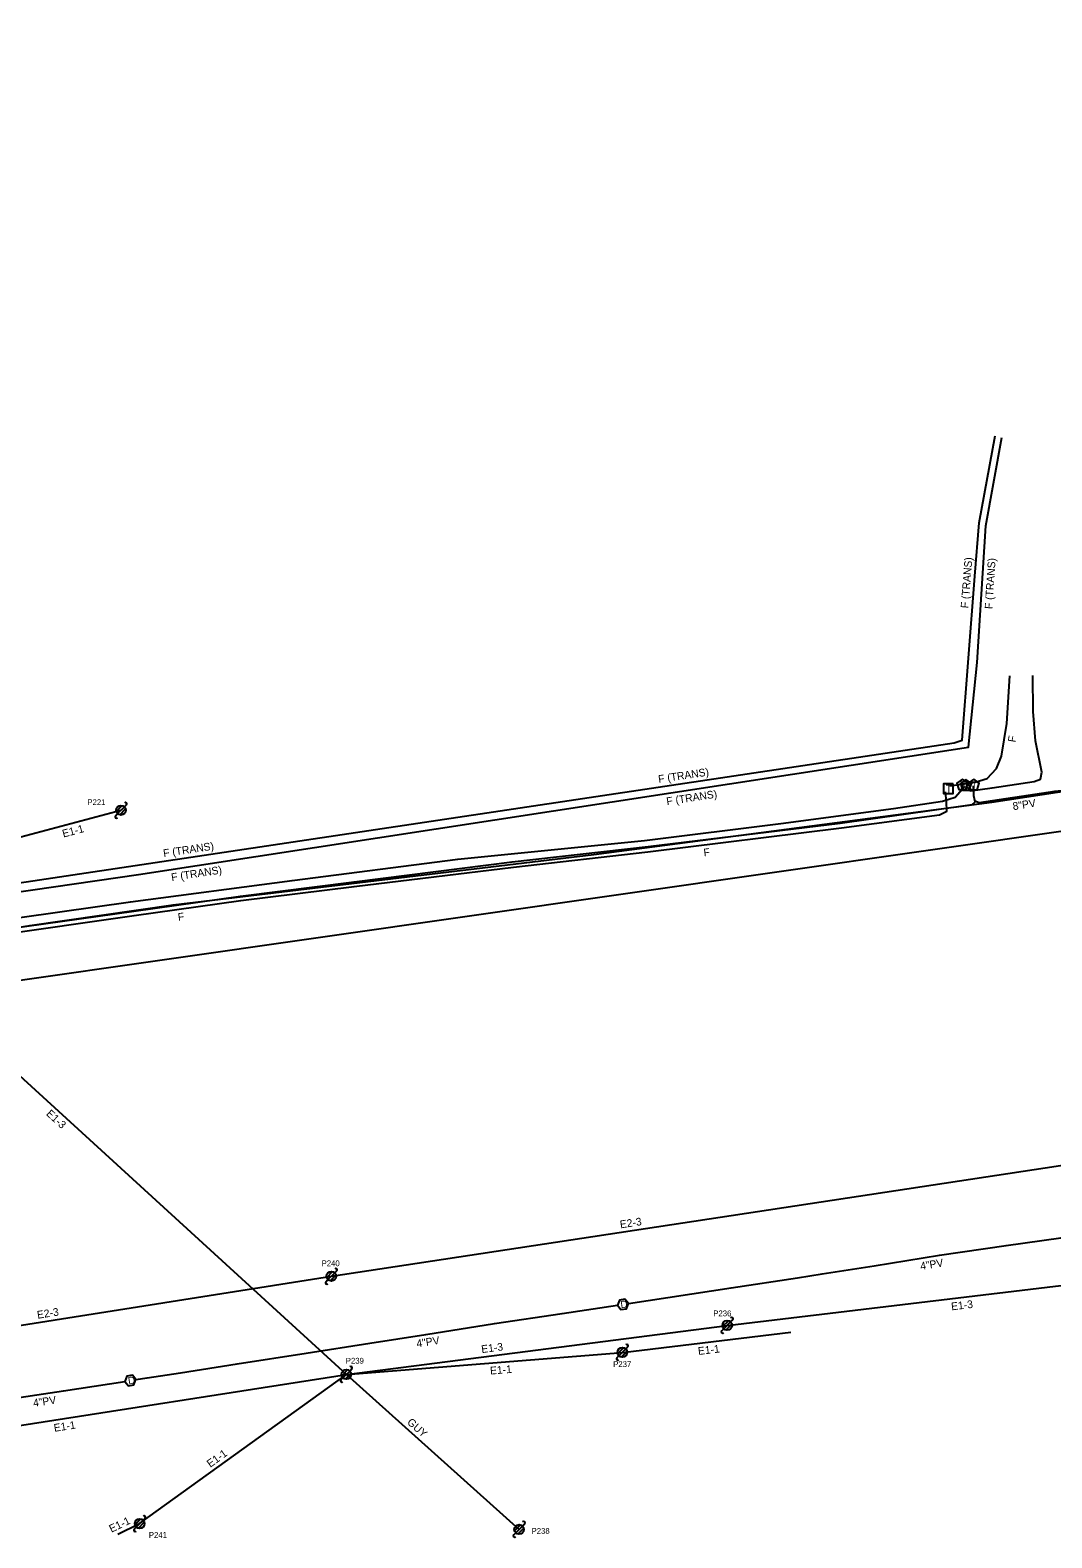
# Model space of a CAD drawing. Extents: x 1614474 to 1865144, y 1098877 to 1212550.
# Drawn here: x 1776287 to 1776816, y 1179819 to 1180599 of the extents above; entities that cross this region are included whole.
import ezdxf

# ---------------------------------------------------------------- set-up
doc = ezdxf.new("R2010")
doc.units = 0
for name, color, linetype in [('BFUSER_FIBERSPAN', 7, 'Continuous'), ('RD_EX_SU_H2O', 7, 'Continuous'), ('RD_EX_SU_Ovhd', 7, 'Continuous'), ('RD_EX_SU_Pole', 7, 'Continuous'), ('RD_EX_SU_Telecom', 7, 'Continuous'), ('RD_EX_SU_TX_H2O', 7, 'Continuous'), ('RD_EX_SU_TX_Pole', 7, 'Continuous'), ('RD_EX_SU_TX_Telecom', 7, 'Continuous')]:
    doc.layers.add(name, color=color, linetype=linetype)

# ---------------------------------------------------------------- blocks, each defined once
blk = doc.blocks.new('SUE_PP')
at = {"layer": 'RD_EX_SU_Pole'}
for p, q in [((-2.41, -0.65), (0.65, 2.41)), ((-1.77, -1.77), (1.77, 1.77)), ((-0.65, -2.41), (2.41, 0.65)), ((1.77, 1.77), (2.83, 2.83)), ((-2.83, -2.83), (-1.77, -1.77))]:
    blk.add_line(p, q, dxfattribs=at)
blk.add_circle((0, 0), 2.5, dxfattribs=at)
for centre, start, end in [((2.3, 3.36), 315, 135), ((-2.3, -3.36), 135, 315)]:
    blk.add_arc(centre, 0.75, start, end, dxfattribs=at)
blk = doc.blocks.new('SUE_TPP')
at = {"layer": 'RD_EX_SU_Telecom'}
blk.add_lwpolyline([(0, 3), (-2.85, 0.93), (-1.76, -2.43), (1.76, -2.43), (2.85, 0.93)], close=True, dxfattribs=at)
blk.add_text('T', height=3.75, dxfattribs=at).set_placement((-1.25, -1.88))
blk = doc.blocks.new('SUE_THH')
at = {"layer": 'RD_EX_SU_Telecom'}
blk.add_lwpolyline([(2.5, 2.5), (-2.5, 2.5), (-2.5, -2.5), (2.5, -2.5)], close=True, dxfattribs=at)
blk.add_text('T', height=4, dxfattribs=at).set_placement((-1.34, -2))

msp = doc.modelspace()

# ---------------------------------------------------------------- linework, layer by layer
at = {"layer": 'BFUSER_FIBERSPAN'}
msp.add_lwpolyline([(1776119.38, 1180084.52), (1776909.44, 1180197.58), (1777549.89, 1180288.26), (1777793.65, 1180334.21), (1778099.34, 1180399.49), (1778312.74, 1180438.72), (1779456.83, 1180598.99)], dxfattribs=at)
at = {"layer": 'RD_EX_SU_H2O'}
for points in [[(1775079.31, 1179947.86), (1775099.56, 1179951.26), (1775135.1, 1179956.75), (1775200.12, 1179966.22), (1775230.46, 1179971.15), (1775265.28, 1179976.78), (1775296.44, 1179981.42), (1775327.06, 1179986.33), (1775627.47, 1180033.75), (1775910.53, 1180076.48), (1776287.14, 1180136.1), (1776361.29, 1180146.68), (1776578.76, 1180172.75), (1776784.59, 1180199.86), (1777026.8, 1180236.7)], [(1776596.66, 1179940.56), (1776649.72, 1179948.66), (1776649.88, 1179948.69), (1776684.14, 1179953.92), (1776696.94, 1179955.9), (1776723.7, 1179960.03), (1776757.53, 1179965.55), (1776792.08, 1179970.65), (1776820.25, 1179974.64), (1776851.76, 1179980.08), (1776859.59, 1179981.3)], [(1776342.02, 1179901.23), (1776347.84, 1179902.14), (1776365.13, 1179904.83), (1776394.3, 1179909.43), (1776429.97, 1179914.93), (1776462.88, 1179920.06), (1776491.84, 1179924.63), (1776527.49, 1179930.19), (1776562.4, 1179935.51), (1776590.95, 1179939.71)], [(1776104.82, 1179864.77), (1776140.68, 1179869.96), (1776175.04, 1179875.44), (1776175.54, 1179875.52), (1776206.34, 1179880.25), (1776240.64, 1179885.5), (1776271.17, 1179890.42), (1776304.63, 1179895.52), (1776336.21, 1179900.32), (1776336.32, 1179900.34)]]:
    msp.add_lwpolyline(points, dxfattribs=at)
for points in [[(1776596.66, 1179940.56), (1776594.87, 1179942.82), (1776592.01, 1179942.4), (1776590.95, 1179939.71), (1776592.74, 1179937.45), (1776595.6, 1179937.87)], [(1776342.02, 1179901.23), (1776340.22, 1179903.48), (1776337.37, 1179903.05), (1776336.32, 1179900.36), (1776338.12, 1179898.11), (1776340.97, 1179898.54)]]:
    msp.add_lwpolyline(points, close=True, dxfattribs=at)
at = {"layer": 'RD_EX_SU_Ovhd'}
for p, q in [((1776282.53, 1180181.83), (1776334.27, 1180195.67)), ((1776171.93, 1180158.93), (1776450.84, 1179903.93)), ((1776443.07, 1179954.72), (1776825.82, 1180012.85)), ((1776195.31, 1179915.49), (1776443.07, 1179954.72)), ((1776647.76, 1179929.28), (1776854.89, 1179953.96)), ((1776450.84, 1179903.93), (1776647.76, 1179929.28)), ((1776593.56, 1179915.33), (1776680.72, 1179925.74)), ((1776450.84, 1179903.93), (1776593.56, 1179915.33)), ((1776170.06, 1179860.01), (1776450.84, 1179903.93)), ((1776343.93, 1179826.81), (1776450.84, 1179903.93)), ((1776450.84, 1179903.93), (1776540.18, 1179823.77)), ((1776332.61, 1179821.4), (1776343.93, 1179826.81))]:
    msp.add_line(p, q, dxfattribs=at)
at = {"layer": 'RD_EX_SU_Pole'}
for p, q in [((1776331.86, 1180195.02), (1776334.92, 1180198.09)), ((1776332.51, 1180193.9), (1776336.04, 1180197.44)), ((1776336.04, 1180197.44), (1776337.1, 1180198.5)), ((1776331.44, 1180192.84), (1776332.51, 1180193.9)), ((1776333.63, 1180193.26), (1776336.69, 1180196.32)), ((1776440.66, 1179954.07), (1776443.72, 1179957.13)), ((1776441.3, 1179952.95), (1776444.84, 1179956.48)), ((1776444.84, 1179956.48), (1776445.9, 1179957.54)), ((1776440.24, 1179951.89), (1776441.3, 1179952.95)), ((1776442.42, 1179952.3), (1776445.49, 1179955.36)), ((1776644.94, 1179926.45), (1776646, 1179927.51)), ((1776645.35, 1179928.63), (1776648.41, 1179931.7)), ((1776646, 1179927.51), (1776649.53, 1179931.05)), ((1776647.12, 1179926.87), (1776650.18, 1179929.93)), ((1776649.53, 1179931.05), (1776650.59, 1179932.11)), ((1776591.15, 1179914.68), (1776594.21, 1179917.75)), ((1776591.8, 1179913.56), (1776595.33, 1179917.1)), ((1776595.33, 1179917.1), (1776596.39, 1179918.16)), ((1776590.74, 1179912.5), (1776591.8, 1179913.56)), ((1776592.92, 1179912.92), (1776595.98, 1179915.98)), ((1776448.01, 1179901.11), (1776449.07, 1179902.17)), ((1776448.42, 1179903.29), (1776451.49, 1179906.35)), ((1776449.07, 1179902.17), (1776452.61, 1179905.7)), ((1776450.19, 1179901.52), (1776453.25, 1179904.58)), ((1776452.61, 1179905.7), (1776453.67, 1179906.76)), ((1776537.76, 1179823.12), (1776540.83, 1179826.18)), ((1776538.41, 1179822), (1776541.95, 1179825.54)), ((1776539.53, 1179821.35), (1776542.59, 1179824.42)), ((1776541.95, 1179825.54), (1776543.01, 1179826.6)), ((1776537.35, 1179820.94), (1776538.41, 1179822))]:
    msp.add_line(p, q, dxfattribs=at)
for centre in [(1776334.27, 1180195.67), (1776443.07, 1179954.72), (1776647.76, 1179929.28), (1776593.56, 1179915.33), (1776450.84, 1179903.93), (1776540.18, 1179823.77)]:
    msp.add_circle(centre, 2.5, dxfattribs=at)
for centre, start, end in [((1776336.57, 1180199.03), 315, 135), ((1776331.97, 1180192.31), 135, 315), ((1776445.37, 1179958.07), 315, 135), ((1776440.77, 1179951.36), 135, 315), ((1776650.06, 1179932.64), 315, 135), ((1776645.47, 1179925.92), 135, 315), ((1776595.86, 1179918.69), 315, 135), ((1776591.27, 1179911.97), 135, 315), ((1776453.14, 1179907.29), 315, 135), ((1776448.54, 1179900.58), 135, 315), ((1776542.48, 1179827.13), 315, 135), ((1776537.88, 1179820.41), 135, 315)]:
    msp.add_arc(centre, 0.75, start, end, dxfattribs=at)
at = {"layer": 'RD_EX_SU_Telecom'}
msp.add_line((1776770.48, 1180208.53), (1776769.39, 1180208.98), dxfattribs=at)
for points in [[(1775914.84, 1180097.06), (1775916.9, 1180103.05), (1775924.57, 1180107.05), (1776072.57, 1180127.73), (1776266.65, 1180155.91), (1776765.03, 1180230.57), (1776769.2, 1180231.88), (1776775.8, 1180316.7), (1776778.02, 1180344.27), (1776786.24, 1180389.18)], [(1775919.62, 1180097.54), (1775923.9, 1180101.6), (1776343.29, 1180162.41), (1776772.57, 1180228.19), (1776777.07, 1180272.08), (1776781.57, 1180342.62), (1776789.82, 1180388.39)], [(1776762.84, 1180208.23), (1776775.94, 1180210.17), (1776782.16, 1180212.07), (1776786.99, 1180217.16), (1776789.58, 1180223.54), (1776792.32, 1180240.53), (1776793.96, 1180265.14)], [(1776771.26, 1180208.33), (1776773.62, 1180205.6), (1776784.77, 1180207.27), (1776806.5, 1180210.45), (1776809.75, 1180211.8), (1776810.43, 1180215.32), (1776807.23, 1180231.45), (1776805.88, 1180246.69), (1776805.84, 1180265.34)], [(1776775.88, 1180200.47), (1776777.97, 1180199.57), (1776817.24, 1180205.57), (1776842.01, 1180208.09), (1776875.22, 1180212.72), (1776921.6, 1180220.69), (1776970.49, 1180228.43), (1777008.72, 1180235.02), (1777046.72, 1180242.58), (1777100.46, 1180251.28), (1777118.79, 1180254.3), (1777119.55, 1180256.67), (1777118.94, 1180263.61)], [(1775758.43, 1180054.01), (1775815.79, 1180062.96), (1775876.25, 1180072.8), (1775920.38, 1180079.5), (1776009.46, 1180093.25), (1776095.75, 1180106.51), (1776181.05, 1180119.62), (1776266.98, 1180133.11), (1776340.93, 1180143.41), (1776396.03, 1180151.23), (1776454.93, 1180158.69), (1776536.61, 1180168.91), (1776606.86, 1180176.97), (1776706.17, 1180189.01), (1776754.94, 1180195.79), (1776774.44, 1180198.67), (1776775.99, 1180199.97), (1776775.3, 1180203.06), (1776775.16, 1180208.34)], [(1775758.91, 1180052.04), (1775816.52, 1180060.6), (1775877.51, 1180069.95), (1775920.73, 1180076.58), (1776009.66, 1180090.52), (1776095.73, 1180103.84), (1776181.09, 1180117.29), (1776267.46, 1180130.73), (1776341.05, 1180141.25), (1776396.24, 1180148.92), (1776454.9, 1180156.29), (1776537.33, 1180166.2), (1776606.7, 1180174.18), (1776706.91, 1180186.49), (1776757.57, 1180193.24), (1776761.33, 1180195.25), (1776761.19, 1180199.99), (1776760.62, 1180205.15)], [(1775778.64, 1180062.09), (1775845.67, 1180072.11), (1775918.69, 1180083.41), (1775976.35, 1180093.46), (1776032.52, 1180102.81), (1776099.55, 1180115.18), (1776147.55, 1180120.58), (1776207.07, 1180128.23), (1776264.72, 1180137.79), (1776339.25, 1180148.31), (1776422.82, 1180159.28), (1776508.45, 1180170.28), (1776604.94, 1180179.98), (1776675.52, 1180188.85), (1776733.78, 1180196.49), (1776759.12, 1180200.38), (1776765.61, 1180202.42), (1776770.56, 1180208.08)]]:
    msp.add_lwpolyline(points, dxfattribs=at)

# ---------------------------------------------------------------- block references
at = {"layer": 'RD_EX_SU_Pole'}
msp.add_blockref('SUE_PP', (1776343.93, 1179826.81), dxfattribs=at)
at = {"layer": 'RD_EX_SU_Telecom'}
for name, p in [('SUE_THH', (1776762.11, 1180206.81)), ('SUE_TPP', (1776769.35, 1180208.76)), ('SUE_TPP', (1776771.17, 1180208.51)), ('SUE_TPP', (1776775.24, 1180208.7))]:
    msp.add_blockref(name, p, dxfattribs=at)

# ---------------------------------------------------------------- texts
at = {"layer": 'RD_EX_SU_H2O'}
for rotation, p in [(8.38011, (1776592.84, 1179938.1)), (8.68201, (1776338.21, 1179898.75))]:
    msp.add_text('D', height=3.75, rotation=rotation, dxfattribs=at).set_placement(p)
at = {"layer": 'RD_EX_SU_Ovhd'}
for s, rotation, p in [('E1-1', 14.97194, (1776304.53, 1180181.5)), ('E1-3', 317.5653, (1776295.31, 1180038.3)), ('E2-3', 8.63677, (1776592.58, 1179979.45)), ('E1-3', 6.79437, (1776763.78, 1179937.06)), ('E2-3', 8.99565, (1776291.21, 1179932.7)), ('E1-3', 7.33435, (1776520.85, 1179914.96)), ('E1-1', 6.81246, (1776632.87, 1179913.98)), ('E1-1', 4.56521, (1776525.27, 1179903.86)), ('E1-1', 8.89044, (1776299.88, 1179874.25)), ('GUY', 318.09784, (1776481.89, 1179878.76)), ('E1-1', 35.80771, (1776380.46, 1179855.63)), ('E1-1', 25.51068, (1776329.32, 1179822.05))]:
    msp.add_text(s, height=4, rotation=rotation, dxfattribs=at).set_placement(p)
at = {"layer": 'RD_EX_SU_TX_H2O'}
for s, rotation, p in [('8"PV', 8.9238, (1776795.7, 1180195.68)), ('4"PV', 9.25481, (1776747.9, 1179957.9)), ('4"PV', 8.85644, (1776487.39, 1179917.87)), ('4"PV', 8.66056, (1776289.14, 1179887.09))]:
    msp.add_text(s, height=4, rotation=rotation, dxfattribs=at).set_placement(p)
at = {"layer": 'RD_EX_SU_TX_Pole'}
for s, p in [('P221', (1776316.91, 1180198.31)), ('P240', (1776438.03, 1179959.89)), ('P236', (1776640.54, 1179934)), ('P239', (1776450.53, 1179909.51)), ('P237', (1776588.79, 1179907.74)), ('P238', (1776546.59, 1179821.51)), ('P241', (1776348.7, 1179819.44))]:
    msp.add_text(s, height=3, dxfattribs=at).set_placement(p)
at = {"layer": 'RD_EX_SU_TX_Telecom'}
for s, rotation, p in [('F (TRANS)', 85.39155, (1776772.44, 1180299.95)), ('F (TRANS)', 86.34952, (1776784.89, 1180299.56)), ('F', 80.84694, (1776796.79, 1180230.57)), ('F (TRANS)', 8.52003, (1776612.38, 1180209.72)), ('F (TRANS)', 8.7121, (1776616.63, 1180198.22)), ('F (TRANS)', 8.52003, (1776356.41, 1180171.38)), ('F', 7.00691, (1776635.78, 1180171.71)), ('F (TRANS)', 8.7121, (1776360.56, 1180158.98)), ('F', 7.91065, (1776363.97, 1180138.38))]:
    msp.add_text(s, height=4, rotation=rotation, dxfattribs=at).set_placement(p)

doc.saveas('drawing.dxf')
